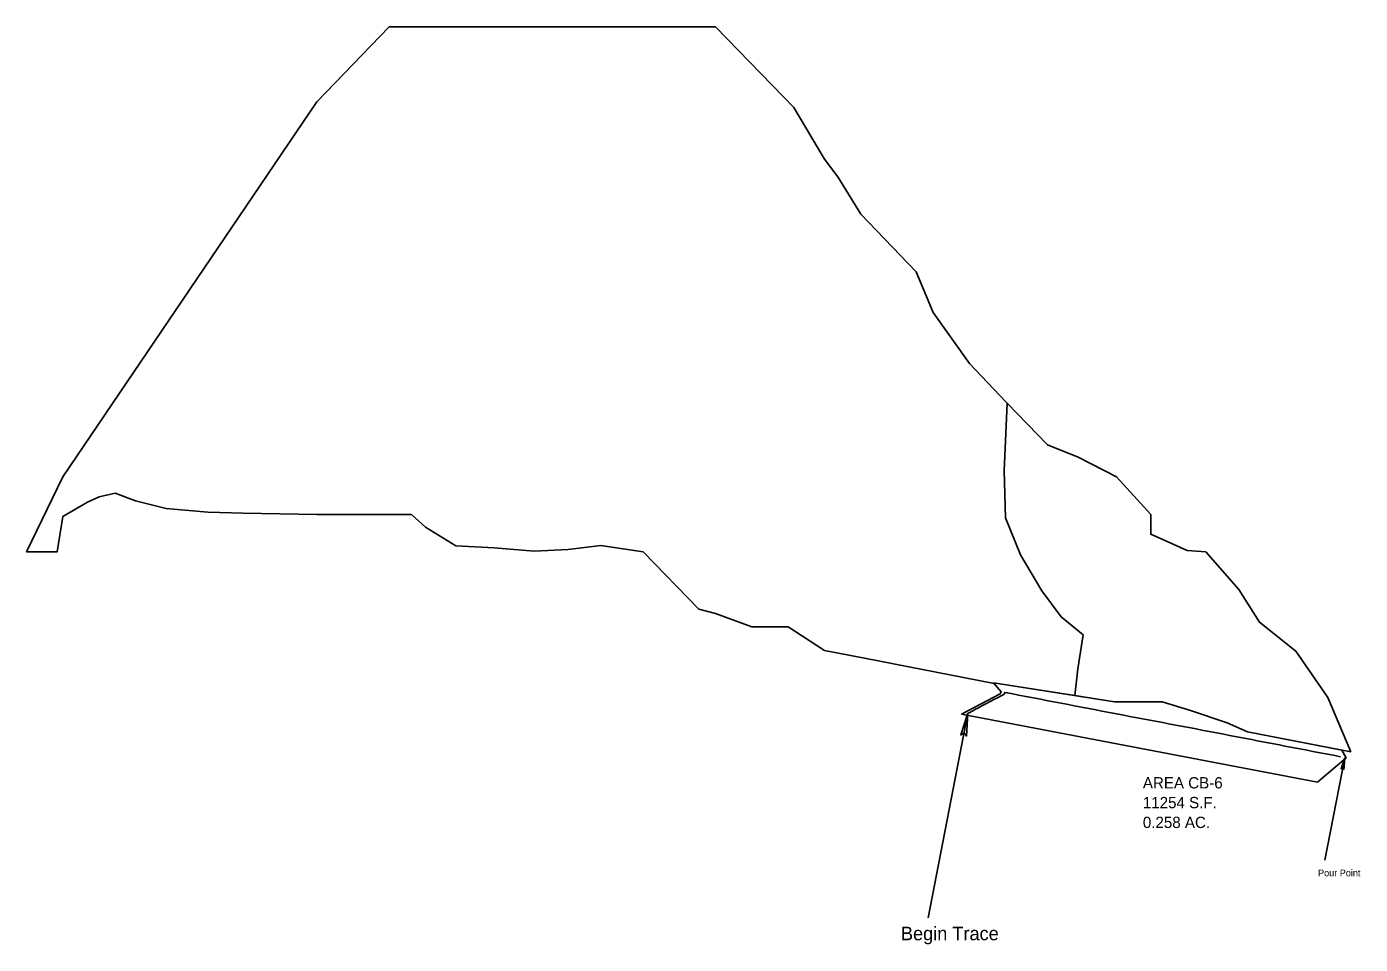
# Model space of a CAD drawing. Extents: x 2334 to 5445, y 2950 to 3762.
import ezdxf

# ---------------------------------------------------------------- set-up
doc = ezdxf.new("R2010")
doc.units = 0
for name, color, linetype in [('Default', 7, 'Continuous'), ('DESIGN - SCRATCH - User 1', 7, 'Continuous'), ('SURVEY - CENTERLINE - Preliminary', 7, 'Continuous'), ('SURVEY - CENTERLINE - Preliminary Text', 7, 'Continuous'), ('SURVEY - DRAINAGE - Area Shapes', 7, 'Continuous')]:
    doc.layers.add(name, color=color, linetype=linetype)

msp = doc.modelspace()

# ---------------------------------------------------------------- linework, layer by layer
at = {"layer": 'DESIGN - SCRATCH - User 1'}
msp.add_line((3500.2, 3115.1), (3482.7, 3024.6), dxfattribs=at)
msp.add_lwpolyline([(3500.2, 3115.1), (3499.5, 3105), (3498.6, 3106.5), (3497, 3105.5)], close=True, dxfattribs=at)
msp.add_lwpolyline([(3500.2, 3115.1), (3499.5, 3105), (3498.6, 3106.5), (3497, 3105.5), (3500.2, 3115.1)], dxfattribs=at)
at = {"layer": 'SURVEY - CENTERLINE - Preliminary'}
msp.add_lwpolyline([(3166.9, 3154.6), (3167.9, 3155.1), (3171.3, 3156.9), (3173.6, 3158.1), (3175.5, 3159.1), (3179.2, 3161.1), (3179.8, 3161.4), (3181.5, 3162.3), (3184, 3163.6), (3184.9, 3164), (3186.6, 3164.9), (3190.5, 3167), (3192.5, 3168.1), (3196.2, 3170), (3196.8, 3170.3), (3198.6, 3171.2), (3199.1, 3172.2), (3199.5, 3173.1), (3201.8, 3172.6), (3206.7, 3171.7), (3211.6, 3170.7), (3216.5, 3169.8), (3221.4, 3168.9), (3226.4, 3167.9), (3231.3, 3167), (3236.2, 3166), (3241.1, 3165.1), (3246, 3164.2), (3250.9, 3163.2), (3255.8, 3162.3), (3260.7, 3161.3), (3265.6, 3160.4), (3270.6, 3159.5), (3275.5, 3158.5), (3280.4, 3157.6), (3285.3, 3156.6), (3290.2, 3155.7), (3295.1, 3154.8), (3300, 3153.8), (3304.9, 3152.9), (3309.8, 3151.9), (3314.8, 3151), (3319.7, 3150.1), (3324.6, 3149.1), (3329.5, 3148.2), (3334.4, 3147.2), (3339.3, 3146.3), (3344.2, 3145.4), (3349.1, 3144.4), (3354, 3143.5), (3359, 3142.5), (3363.9, 3141.6), (3368.8, 3140.7), (3373.7, 3139.7), (3378.6, 3138.8), (3383.5, 3137.8), (3388.4, 3136.9), (3393.3, 3136), (3398.2, 3135), (3403.2, 3134.1), (3408.1, 3133.1), (3413, 3132.2), (3417.9, 3131.3), (3422.8, 3130.3), (3427.7, 3129.4), (3432.6, 3128.4), (3437.5, 3127.5), (3442.4, 3126.6), (3447.3, 3125.6), (3452.3, 3124.7), (3457.2, 3123.7), (3462.1, 3122.8), (3467, 3121.9), (3471.9, 3120.9), (3476.8, 3120), (3481.7, 3119), (3486.6, 3118.1), (3491.5, 3117.2), (3496.5, 3116.2)], dxfattribs=at)
at = {"layer": 'SURVEY - CENTERLINE - Preliminary Text'}
msp.add_line((3166.9, 3154.6), (3131.8, 2973.7), dxfattribs=at)
msp.add_lwpolyline([(3166.9, 3154.6), (3165.5, 3134.4), (3163.6, 3137.4), (3160.5, 3135.4)], close=True, dxfattribs=at)
msp.add_lwpolyline([(3166.9, 3154.6), (3165.5, 3134.4), (3163.6, 3137.4), (3160.5, 3135.4), (3166.9, 3154.6)], dxfattribs=at)
at = {"layer": 'SURVEY - DRAINAGE - Area Shapes'}
for p, q in [((3190.1, 3180.9), (3075.4, 3203.5)), ((3476, 3093.7), (3161.3, 3153.9))]:
    msp.add_line(p, q, dxfattribs=at)
for points in [[(2334.2, 3297.4), (2366.3, 3363.8), (2590.9, 3695.6), (2655, 3762)], [(2655, 3762), (2943.7, 3762)], [(2943.7, 3762), (3003.6, 3700), (3012.9, 3690.4), (3039.9, 3644.9), (3051.9, 3629.3), (3072, 3596.1), (3121.2, 3545.1)], [(3121.2, 3545.1), (3136.2, 3509.1), (3168.2, 3464.1), (3200.3, 3430.1), (3201.6, 3428.8)], [(3201.6, 3428.8), (3199, 3369.1), (3200.2, 3327.4), (3213.4, 3294.7), (3232.2, 3262.9), (3249.3, 3239.9), (3268.9, 3223.9), (3264.1, 3193.8), (3261.3, 3170.2)], [(3261.3, 3170.2), (3264.1, 3193.8), (3268.9, 3223.9), (3249.3, 3239.9), (3232.2, 3262.9), (3213.4, 3294.7), (3200.2, 3327.4), (3199, 3369.1), (3201.6, 3428.8)], [(3201.6, 3428.8), (3237.1, 3392), (3264.5, 3381.2), (3298.4, 3363.8), (3328.6, 3330.6), (3328.6, 3313), (3360.7, 3298.5), (3377.2, 3297.4), (3406.6, 3264.2), (3424.9, 3235.1), (3456.9, 3209.6), (3485.2, 3168.6), (3505.7, 3120.6)], [(2928.7, 3246.6), (2879.5, 3297.4), (2842, 3303), (2813.3, 3299.6), (2783.3, 3297.9), (2747.8, 3301), (2713.9, 3302.8), (2687.1, 3319.1), (2674.6, 3330.6), (2590.9, 3330.6), (2525.7, 3331.6), (2494.6, 3332.5), (2457.6, 3335.7), (2430.5, 3342.6), (2412.4, 3349.2), (2398.4, 3346), (2387.9, 3341.4), (2366.3, 3328.7), (2361.1, 3297.4), (2334.2, 3297.4)], [(3075.4, 3203.5), (3039.9, 3210.2), (3007.9, 3231), (2975.8, 3231), (2943.7, 3243), (2928.7, 3246.6)], [(3161.3, 3153.9), (3195.4, 3171.8), (3196.4, 3173.7), (3189.6, 3181.6)], [(3189.6, 3181.6), (3296.5, 3164.6), (3338.8, 3164.6), (3363, 3157.3), (3396.3, 3146.2), (3414.1, 3138.3), (3497.7, 3122.1)], [(3261.3, 3170.2), (3189.6, 3181.6)], [(3505.7, 3120.6), (3414.1, 3138.3), (3396.3, 3146.2), (3363, 3157.3), (3338.8, 3164.6), (3296.5, 3164.6), (3261.3, 3170.2)], [(3497.7, 3122.1), (3501.4, 3115.3), (3476, 3093.7)]]:
    msp.add_lwpolyline(points, dxfattribs=at)

# ---------------------------------------------------------------- texts
at = {"layer": 'Default'}
for s, p in [('AREA CB-6', (3321.6, 3088.1)), ('11254 S.F.', (3321.6, 3070.6)), ('0.258 AC.', (3321.6, 3053.1))]:
    msp.add_text(s, height=10, dxfattribs=at).set_placement(p)
at = {"layer": 'DESIGN - SCRATCH - User 1'}
msp.add_text('Pour Point', height=6, dxfattribs=at).set_placement((3476.6, 3010.4))
at = {"layer": 'SURVEY - CENTERLINE - Preliminary Text'}
msp.add_text('Begin Trace ', height=12, dxfattribs=at).set_placement((3107.6, 2953.8))

doc.saveas('drawing.dxf')
